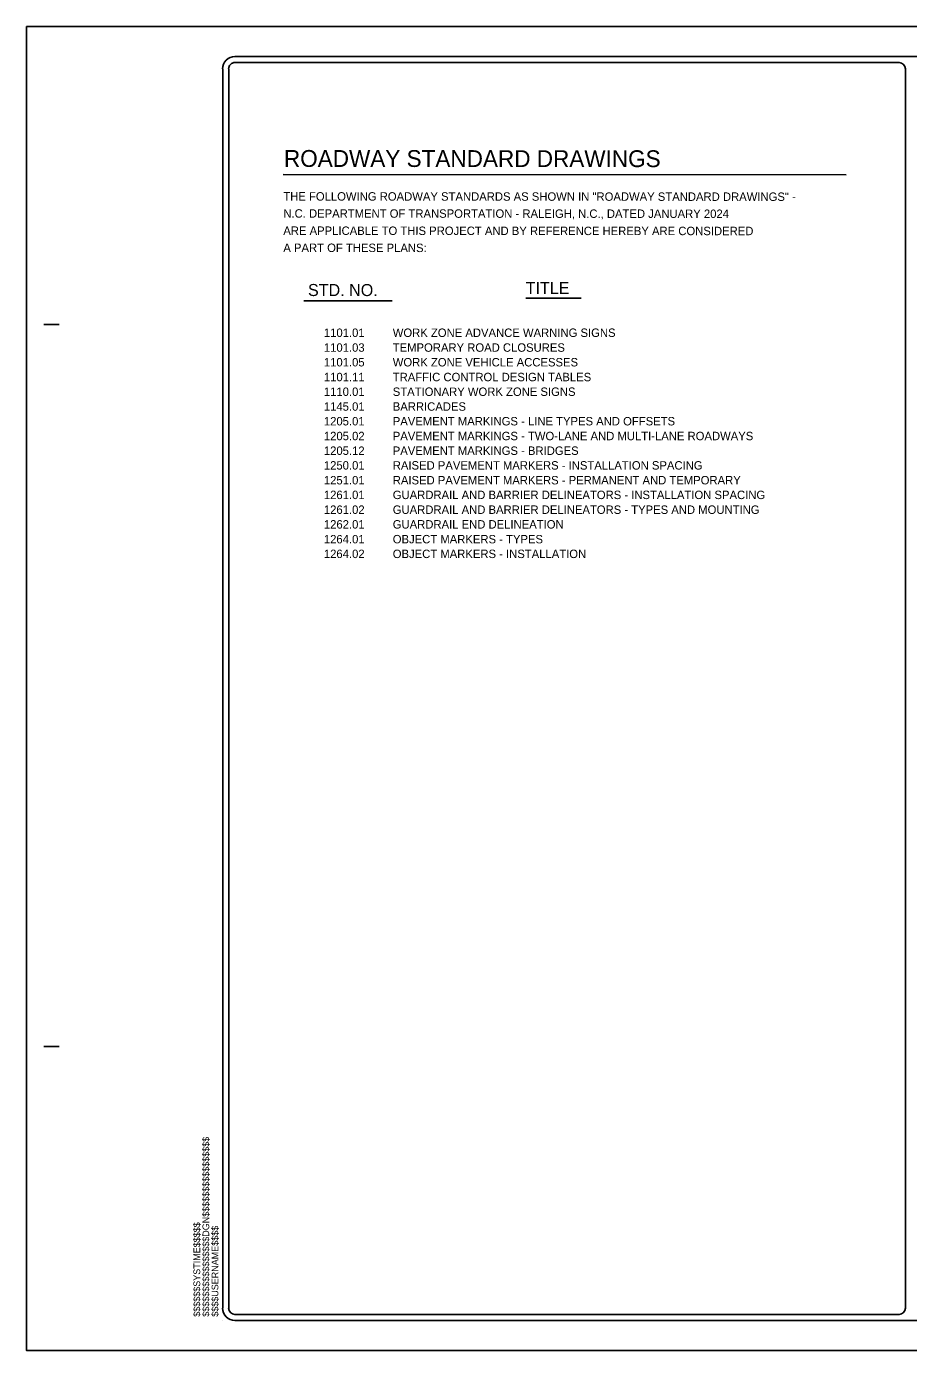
# Model space of a CAD drawing. Extents: x 198 to 2213, y -571 to 529.
# Drawn here: x 198 to 931, y -571 to 529 of the extents above; entities that cross this region are included whole.
import ezdxf

# ---------------------------------------------------------------- set-up
doc = ezdxf.new("R2010")
doc.units = 0
doc.layers.add('Sheet Data Field CELL', color=7, linetype='Continuous')
doc.layers.add('Sheet PE Seal CELL', color=7, linetype='Continuous')

msp = doc.modelspace()

# ---------------------------------------------------------------- linework, layer by layer
at = {"layer": 'Sheet Data Field CELL'}
for points in [[(197.7, -570.9), (1885.7, -570.9), (1885.7, 529.1), (197.7, 529.1)], [(197.7, 529.1), (1885.7, 529.1), (1885.7, -570.9), (197.7, -570.9)]]:
    msp.add_lwpolyline(points, close=True, dxfattribs=at)
at = {"layer": 'Sheet PE Seal CELL'}
for p, q in [((1850.4, 504.1), (370.9, 504.1)), ((922.8, 499.1), (370.9, 499.1)), ((360.7, 493.9), (360.7, -535.6)), ((365.7, 493.9), (365.7, -535.6)), ((928.1, 493.9), (928.1, -535.6)), ((411, 406.3), (878.7, 406)), ((428.2, 301.2), (501.5, 301.1)), ((442.2, 301.2), (442.2, 301.2)), ((442.2, 301.2), (442.2, 301.2)), ((612.7, 303.5), (658.7, 303.5)), ((212.2, 281.6), (224.7, 281.6)), ((212.2, -318.4), (224.7, -318.4)), ((360.7, -545.9), (360.7, -545.9)), ((370.9, -540.9), (922.8, -540.9)), ((370.9, -545.9), (1850.4, -545.9))]:
    msp.add_line(p, q, dxfattribs=at)
for centre, radius, start, end in [((370.9, 493.9), 10.3, 89.9972, 180), ((370.9, 493.9), 5.29, 89.9972, 180), ((922.8, 493.9), 5.29, 0.0001, 89.9995), ((370.9, -535.6), 10.3, 180, 270), ((370.9, -535.6), 5.29, 180, 270), ((922.8, -535.6), 5.29, 270.0005, 359.9999)]:
    msp.add_arc(centre, radius, start, end, dxfattribs=at)

# ---------------------------------------------------------------- texts
for s, height, rotation, p in [('ROADWAY STANDARD DRAWINGS', 13.999, 359.9598, (411.6, 412.5)), ('THE FOLLOWING ROADWAY STANDARDS AS SHOWN IN "ROADWAY STANDARD DRAWINGS" -', 7, 359.9598, (411.1, 384.5)), ('N.C. DEPARTMENT OF TRANSPORTATION - RALEIGH, N.C., DATED JANUARY 2024', 7, 359.9598, (411.1, 370.3)), ('ARE APPLICABLE TO THIS PROJECT AND BY REFERENCE HEREBY ARE CONSIDERED', 7, 359.9598, (411.1, 356)), ('A PART OF THESE PLANS:', 7, 359.9598, (411.1, 341.8)), ('STD. NO.', 10, 359.9598, (431.6, 305.2)), ('TITLE', 10, 359.9598, (612.5, 306.9)), ('$$$$$$$$$$$$$$$$DGN$$$$$$$$$$$$$$$$', 5.584, 90, (349.5, -542.8)), ('$$$$$$SYSTIME$$$$$', 5.584, 90, (342, -542.8)), ('$$$$USERNAME$$$$', 5.584, 90, (357.1, -542.8))]:
    msp.add_text(s, height=height, rotation=rotation, dxfattribs=at).set_placement(p)
for s, p in [('1101.01         WORK ZONE ADVANCE WARNING SIGNS', (444.8, 271.2)), ('1101.03         TEMPORARY ROAD CLOSURES', (444.8, 258.9)), ('1101.05         WORK ZONE VEHICLE ACCESSES', (444.8, 246.7)), ('1101.11         TRAFFIC CONTROL DESIGN TABLES', (444.8, 234.4)), ('1110.01         STATIONARY WORK ZONE SIGNS', (444.8, 222.2)), ('1145.01         BARRICADES', (444.8, 209.9)), ('1205.01         PAVEMENT MARKINGS - LINE TYPES AND OFFSETS', (444.8, 197.7)), ('1205.02         PAVEMENT MARKINGS - TWO-LANE AND MULTI-LANE ROADWAYS', (444.8, 185.4)), ('1205.12         PAVEMENT MARKINGS - BRIDGES', (444.8, 173.2)), ('1250.01         RAISED PAVEMENT MARKERS - INSTALLATION SPACING', (444.8, 161)), ('1251.01         RAISED PAVEMENT MARKERS - PERMANENT AND TEMPORARY ', (444.8, 148.7)), ('1261.01         GUARDRAIL AND BARRIER DELINEATORS - INSTALLATION SPACING', (444.8, 136.5)), ('1261.02         GUARDRAIL AND BARRIER DELINEATORS - TYPES AND MOUNTING ', (444.8, 124.2)), ('1262.01         GUARDRAIL END DELINEATION', (444.8, 112)), ('1264.01         OBJECT MARKERS - TYPES', (444.8, 99.7)), ('1264.02         OBJECT MARKERS - INSTALLATION', (444.8, 87.5))]:
    msp.add_text(s, height=7, dxfattribs=at).set_placement(p)

doc.saveas('drawing.dxf')
